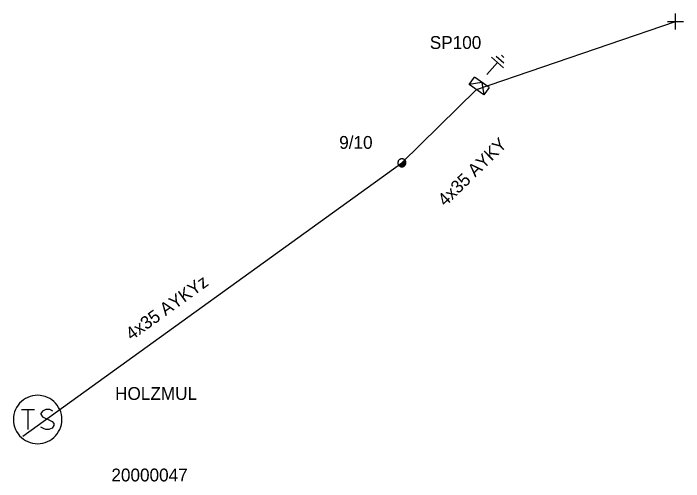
# Model space of a CAD drawing. Extents: x -717562 to -713845, y -1151196 to -1143903.
# Drawn here: x -714521.2 to -714468.9, y -1148393.5 to -1148357 of the extents above; entities that cross this region are included whole.
import ezdxf

# ---------------------------------------------------------------- set-up
doc = ezdxf.new("R2010")
doc.units = 0
for name, color, linetype in [('Vrstva 1', 7, 'Continuous'), ('Vrstva 12', 7, 'Continuous'), ('Vrstva 13', 7, 'Continuous'), ('Vrstva 14', 7, 'Continuous'), ('Vrstva 15', 7, 'Continuous'), ('Vrstva 2', 7, 'Continuous'), ('Vrstva 25', 7, 'Continuous'), ('Vrstva 26', 7, 'Continuous'), ('Vrstva 27', 7, 'Continuous'), ('Vrstva 31', 7, 'Continuous'), ('Vrstva 33', 7, 'Continuous'), ('Vrstva 34', 7, 'Continuous'), ('Vrstva 52', 7, 'Continuous'), ('Vrstva 53', 7, 'Continuous'), ('Vrstva 54', 7, 'Continuous'), ('Vrstva 59', 7, 'Continuous'), ('Vrstva 6', 7, 'Continuous'), ('Vrstva 9', 7, 'Continuous')]:
    doc.layers.add(name, color=color, linetype=linetype)

# ---------------------------------------------------------------- blocks, each defined once
blk = doc.blocks.new('NN440')
at = {"layer": 'Vrstva 2'}
for points in [[(0.63, 0), (0.63, 0.06), (0.62, 0.13), (0.6, 0.19), (0.58, 0.25), (0.55, 0.31), (0.51, 0.37), (0.47, 0.42), (0.42, 0.46), (0.37, 0.51), (0.32, 0.54), (0.26, 0.57), (0.2, 0.59), (0.13, 0.61), (0.07, 0.62), (0, 0.63), (-0.06, 0.62), (-0.13, 0.61), (-0.19, 0.59), (-0.26, 0.57), (-0.31, 0.54), (-0.37, 0.51), (-0.42, 0.46), (-0.47, 0.42), (-0.51, 0.37), (-0.54, 0.31), (-0.57, 0.25), (-0.6, 0.19), (-0.62, 0.13), (-0.63, 0.06), (-0.63, 0), (-0.63, -0.07), (-0.62, -0.14), (-0.6, -0.2), (-0.57, -0.26), (-0.54, -0.32), (-0.51, -0.37), (-0.47, -0.43), (-0.42, -0.47), (-0.37, -0.51), (-0.31, -0.55), (-0.26, -0.58), (-0.19, -0.6), (-0.13, -0.62), (-0.06, -0.63), (0, -0.63), (0.07, -0.63), (0.13, -0.62), (0.2, -0.6), (0.26, -0.58), (0.32, -0.55), (0.37, -0.51), (0.42, -0.47), (0.47, -0.43), (0.51, -0.37), (0.55, -0.32), (0.58, -0.26), (0.6, -0.2), (0.62, -0.14), (0.63, -0.07), (0.63, 0)], [(-0.63, 0), (0.63, 0)], [(-0.6, -0.18), (0.57, -0.18)], [(-0.51, -0.32), (0.5, -0.32)], [(-0.37, -0.47), (0.35, -0.47)]]:
    blk.add_lwpolyline(points, dxfattribs=at)
blk = doc.blocks.new('NN800')
at = {"layer": 'Vrstva 1'}
for points in [[(-0.442, 0.442), (0.442, -0.442)], [(-0.442, -0.442), (0.442, 0.442)]]:
    blk.add_lwpolyline(points, dxfattribs=at)
blk = doc.blocks.new('NN630')
at = {"layer": 'Vrstva 9'}
for points in [[(-0.003, -0.7), (-0.703, 0)], [(-0.703, -0.7), (-0.703, 0), (0.697, 0), (0.697, -0.7)], [(-0.003, -0.7), (0.697, 0)], [(-0.703, -0.7), (0.697, -0.7)]]:
    blk.add_lwpolyline(points, dxfattribs=at)
blk = doc.blocks.new('NN810')
at = {"layer": 'Vrstva 14'}
for points in [[(0.004, -0.64), (0.004, -1.89)], [(0.629, -1.89), (-0.621, -1.89)], [(0.388, -2.2), (-0.399, -2.2)], [(0.004, -2.515), (-0.124, -2.515)], [(0.137, -2.515), (0.004, -2.515)]]:
    blk.add_lwpolyline(points, dxfattribs=at)
blk = doc.blocks.new('NN610')
at = {"layer": 'Vrstva 6'}
for points in [[(1.883, -0.001), (1.872, 0.196), (1.841, 0.392), (1.79, 0.583), (1.718, 0.768), (1.629, 0.943), (1.521, 1.109), (1.397, 1.263), (1.257, 1.403), (1.103, 1.527), (0.937, 1.635), (0.761, 1.725), (0.577, 1.796), (0.19, 1.878), (0.19, 1.878), (-0.007, 1.889), (-0.205, 1.878), (-0.401, 1.847), (-0.591, 1.796), (-0.777, 1.725), (-0.952, 1.635), (-1.118, 1.527), (-1.272, 1.403), (-1.412, 1.263), (-1.536, 1.109), (-1.644, 0.943), (-1.734, 0.768), (-1.805, 0.583), (-1.856, 0.392), (-1.887, 0.196), (-1.898, -0.001), (-1.887, -0.199), (-1.856, -0.395), (-1.805, -0.585), (-1.734, -0.77), (-1.644, -0.946), (-1.536, -1.112), (-1.411, -1.266), (-1.272, -1.405), (-1.118, -1.53), (-0.952, -1.638), (-0.776, -1.728), (-0.591, -1.799), (-0.401, -1.85), (-0.205, -1.881), (-0.007, -1.892), (0.19, -1.881), (0.385, -1.85), (0.577, -1.799), (0.761, -1.728), (0.937, -1.638), (1.103, -1.53), (1.257, -1.405), (1.397, -1.266), (1.521, -1.112), (1.629, -0.946), (1.718, -0.77), (1.79, -0.585), (1.841, -0.395), (1.872, -0.199), (1.883, -0.001)], [(-1.269, 0.782), (-0.261, 0.782)], [(-0.765, 0.782), (-0.765, -0.792)], [(1.188, 0.656), (0.936, 0.782), (0.621, 0.782), (0.369, 0.656), (0.243, 0.468), (0.243, 0.404), (0.369, 0.216), (1.125, -0.162), (1.251, -0.32), (1.251, -0.478), (1.125, -0.666), (0.873, -0.792), (0.621, -0.792), (0.495, -0.73), (0.243, -0.604)]]:
    blk.add_lwpolyline(points, dxfattribs=at)

msp = doc.modelspace()

# ---------------------------------------------------------------- linework, layer by layer
at = {"layer": 'Vrstva 52'}
for points in [[(-714490.9, -1148368.65), (-714485.079, -1148362.944)], [(-714520.44, -1148389.96), (-714490.9, -1148368.65)]]:
    msp.add_lwpolyline(points, dxfattribs=at)
at = {"layer": 'Vrstva 59'}
msp.add_lwpolyline([(-714485.08, -1148362.944), (-714469.56, -1148357.63)], dxfattribs=at)

# ---------------------------------------------------------------- block references
at = {"layer": 'Vrstva 13', "xscale": 0.5, "yscale": 0.5, "rotation": 33.44446382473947}
msp.add_blockref('NN440', (-714490.9, -1148368.65), dxfattribs=at)
at = {"layer": 'Vrstva 15', "rotation": 139.23130837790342}
msp.add_blockref('NN810', (-714484.679, -1148362.263), dxfattribs=at)
at = {"layer": 'Vrstva 25'}
msp.add_blockref('NN610', (-714519.29, -1148388.66), dxfattribs=at)
at = {"layer": 'Vrstva 31', "rotation": 144.125847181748}
msp.add_blockref('NN630', (-714485.08, -1148362.944), dxfattribs=at)
at = {"layer": 'Vrstva 34', "rotation": 45}
msp.add_blockref('NN800', (-714469.56, -1148357.63), dxfattribs=at)

# ---------------------------------------------------------------- texts
at = {"layer": 'Vrstva 12'}
msp.add_text('9/10', height=1, dxfattribs=at).set_placement((-714495.786, -1148367.562))
at = {"layer": 'Vrstva 26'}
msp.add_text('20000047', height=1, dxfattribs=at).set_placement((-714513.548, -1148393.488))
at = {"layer": 'Vrstva 27'}
msp.add_text('HOLZMUL', height=1, dxfattribs=at).set_placement((-714513.259, -1148387.135))
at = {"layer": 'Vrstva 33'}
msp.add_text('SP100', height=1, dxfattribs=at).set_placement((-714488.723, -1148359.774))
at = {"layer": 'Vrstva 53'}
msp.add_text('4x35 AYKYz', height=1, rotation=35.807, dxfattribs=at).set_placement((-714511.977, -1148382.534))
at = {"layer": 'Vrstva 54'}
msp.add_text('4x35 AYKY', height=1, rotation=44.428, dxfattribs=at).set_placement((-714487.515, -1148372.103))

doc.saveas('drawing.dxf')
